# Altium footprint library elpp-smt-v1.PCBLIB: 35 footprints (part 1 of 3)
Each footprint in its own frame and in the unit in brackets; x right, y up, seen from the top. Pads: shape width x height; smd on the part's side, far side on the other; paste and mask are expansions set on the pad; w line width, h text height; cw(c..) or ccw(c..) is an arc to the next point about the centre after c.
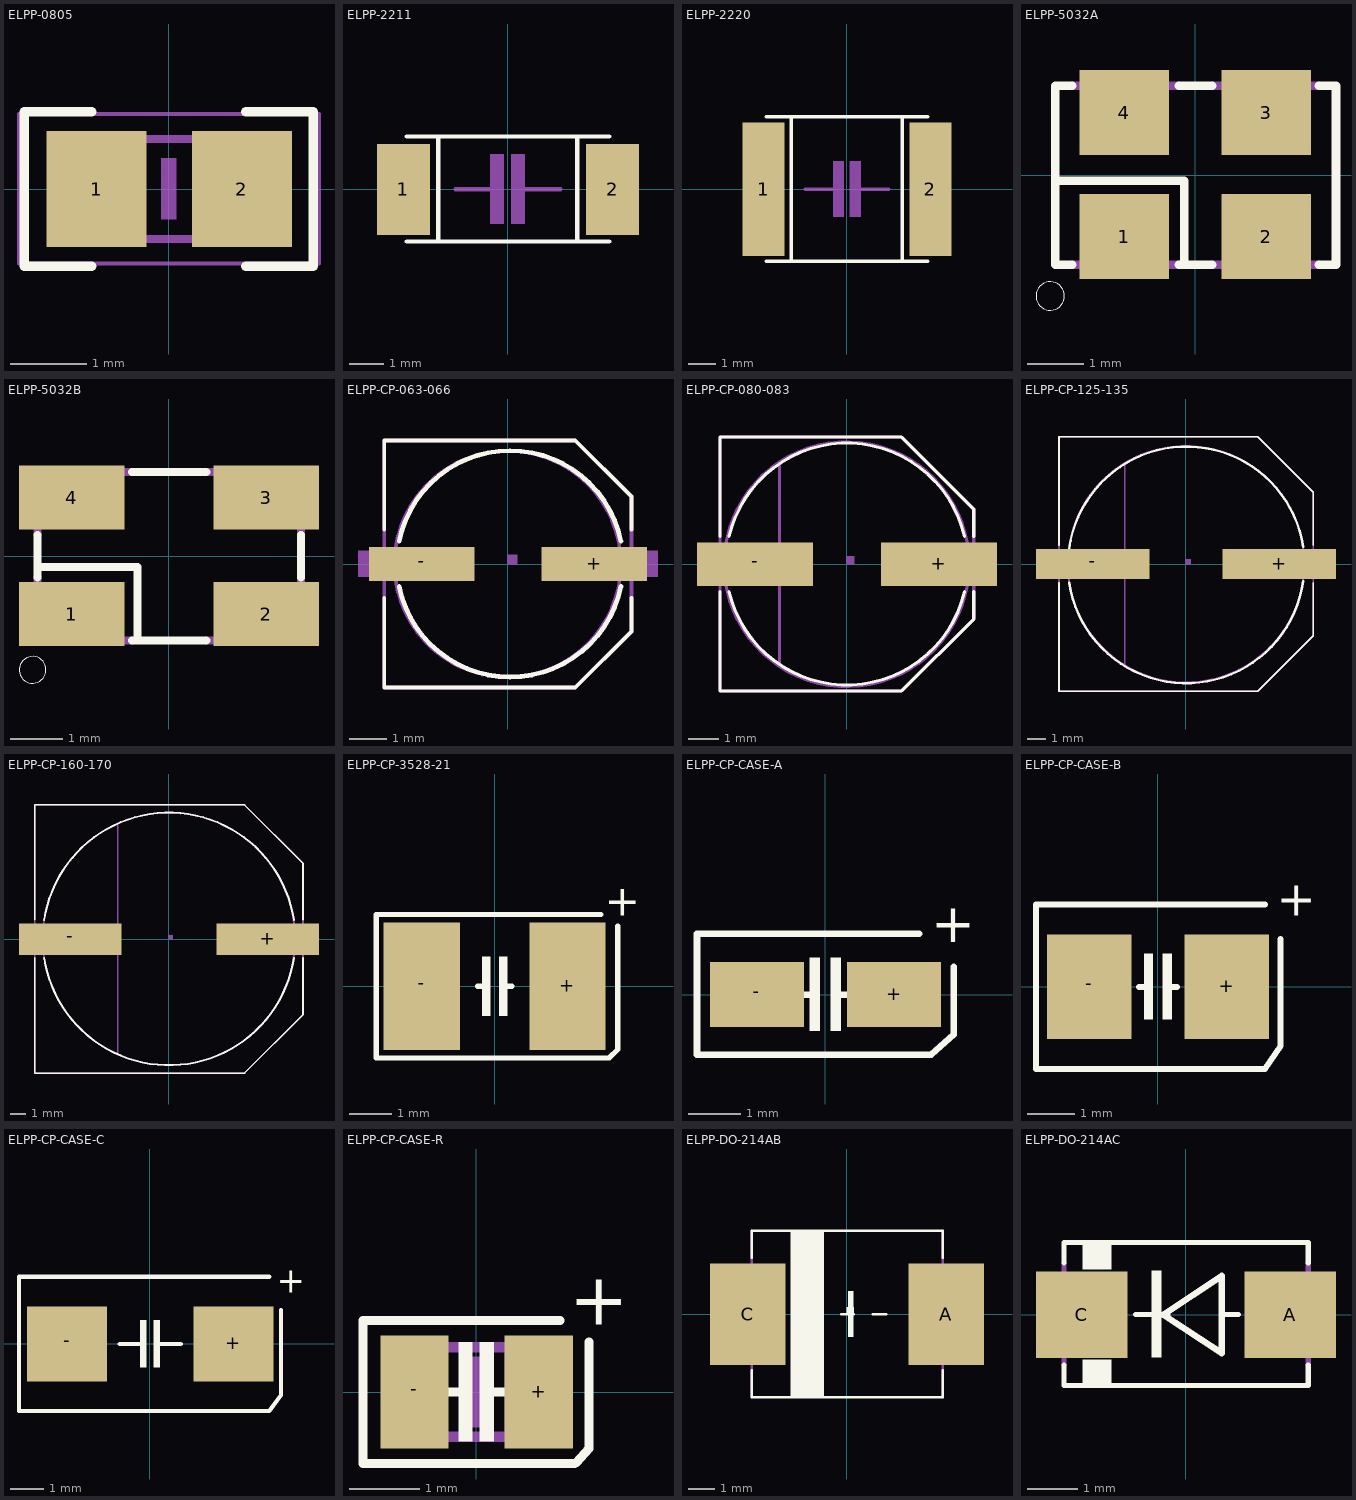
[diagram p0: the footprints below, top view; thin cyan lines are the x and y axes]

## ELPP-0805 [mil]
pads (2):
  rect 52x60 smd: 1(-37.4,0) 2(38,0)
Top Overlay:
  lines w5: -40,-40 -75,-40 -75,40 -40,40 ; 40,-40 75,-40 75,40 40,40
Mechanical 2:
  text ">NAME" at 85,-25 h42.5
Mechanical 4:
  text ">VALUE" at -50,-100 h42.5
Mechanical 6:
  rectangle: -3.94,-15.75 4,16
Mechanical 16:
  rectangle: -43,-28.5 -13.47,29
  rectangle: 14,-28.5 44,29
  lines w4: -15,26 15,26 ; -14.02,-25.98 15,-25.98
Mechanical 27:
  lines w2: -77.68,-38.7 78,-38.7 78,39 -77.68,39 -77.68,-38.7

## ELPP-2211 [mil]
pads (2):
  rect 60x103 smd: 1(-118.11,0) 2(119,0)
Top Overlay:
  lines w5: -114.17,-59.06 -78.74,-59.06 ; -114.17,60 -78.74,60 ; 115,-59.06 79,-59.06 ; 115,60 79,60 ; -78.74,-59.06 79,-59.06 ; -78.74,-59.06 -78.74,60 ; -78.74,60 79,60 ; 79,-59.06 79,60
Mechanical 2:
  text ">NAME" at 158,-23.62 h42.5
Mechanical 4:
  rectangle: 4,-39.37 20,40
  rectangle: -19.68,-39.37 -3.94,40
  lines w5: -59.06,0 -15.75,0 ; 16,0 60,0
  text ">VALUE" at -118.11,-122.05 h42.5

## ELPP-2220 [mil]
pads (2):
  rect 60x189 smd: 1(-118.11,0) 2(119,0)
Top Overlay:
  lines w5: -114.17,-102.36 -78.74,-102.36 ; -114.17,103 -78.74,103 ; 115,-102.36 79,-102.36 ; 115,103 79,103 ; -78.74,-102.36 79,-102.36 ; -78.74,-102.36 -78.74,103 ; -78.74,103 79,103 ; 79,-102.36 79,103
Mechanical 2:
  text ">NAME" at 158,-23.62 h42.5
Mechanical 4:
  rectangle: 4,-39.37 20,40
  rectangle: -19.68,-39.37 -3.94,40
  lines w5: -59.06,0 -15.75,0 ; 16,0 60,0
  text ">VALUE" at -116.93,-160.63 h42.5

## ELPP-5032A [mil]
pads (4):
  rect 63x60 smd: 1(-50,-43.31) 2(50,-43.31) 3(50,44) 4(-50,44)
Top Overlay:
  circle w0: c-102.13,-85.12 r10
  lines w6: -86.61,-62.99 -98.43,-62.99 -98.43,-3.94 ; -86.61,63 -98.43,63 -98.43,-3.94 ; -11.81,-62.99 -7.87,-62.99 ; -11.81,63 12,63 ; 12,-62.99 -7.87,-62.99 ; 87,-62.99 99,-62.99 99,63 87,63 ; -98.43,-3.94 -7.87,-3.94 -7.87,-62.99
Mechanical 2:
  text ">NAME" at 125,-23.23 h42.5
Mechanical 4:
  text ">VALUE" at -70.31,-134.17 h42.5
Mechanical 16:
  lines w6: -86.61,-62.99 -11.81,-62.99 ; -86.61,63 -11.81,63 ; 12,-62.99 87,-62.99 ; 12,63 87,63

## ELPP-5032B [mil]
pads (4):
  rect 79x48 smd: 1(-72.83,-43.31) 2(73,-43.31) 3(73,44) 4(-72.83,44)
Top Overlay:
  circle w0: c-102.13,-85.12 r10
  lines w6: -98.43,-15.75 -98.43,-7.87 ; -98.43,16 -98.43,-7.87 ; -27.56,-62.99 -23.62,-62.99 ; -27.56,63 28,63 ; 28,-62.99 -23.62,-62.99 ; 99,-15.75 99,16 ; -98.43,-7.87 -23.62,-7.87 -23.62,-62.99
Mechanical 2:
  text ">NAME" at 125,-23.23 h42.5
Mechanical 4:
  text ">VALUE" at -70.31,-134.17 h42.5
Mechanical 16:
  lines w6: -98.43,-15.75 -98.43,-62.99 -27.56,-62.99 ; -98.43,16 -98.43,63 -27.56,63 ; 28,-62.99 99,-62.99 99,-15.75 ; 28,63 99,63 99,16

## ELPP-CP-063-066 [mil]
pads (2):
  rect 111x36 smd: +(91,0) -(-90.55,0)
Top Overlay:
  lines w4: -129.92,-35.43 -129.92,-129.92 71,-129.92 130,-70.87 130,-35.43 ; -129.92,36 -129.92,130 71,130 130,71 130,36
  lines w5: -114.17,-23.62 ccw(c2.41,0.09) 119,-23.62 ; -114.17,24 cw(c2.41,0.29) 119,24
Mechanical 2:
  text ">NAME" at 174,-23.62 h42.5
Mechanical 4:
  text ">VALUE" at -70.87,-87.6 h42.5
Mechanical 16:
  circle w4: c0,0 r119
  rectangle: -157.48,-13.78 -129.92,14
  rectangle: 130,-13.78 158,14
  region: 0,0 10,0 10,10 0,10
  lines w4: -129.92,-129.92 71,-129.92 130,-70.87 130,71 71,130 -129.92,130 -129.92,-129.92

## ELPP-CP-080-083 [mil]
pads (2):
  rect 150x56 smd: +(119,0) -(-118.11,0)
Top Overlay:
  lines w4: -163.39,-35.43 -163.39,-163.39 71,-163.39 164,-70.87 164,-35.43 ; -163.39,36 -163.39,164 71,164 164,71 164,36 ; -151.57,-35.43 ccw(c0.21,0.05) 152,-35.43 ; -151.57,36 cw(c0.21,0.52) 152,36
Mechanical 2:
  text ">NAME" at 209,-23.62 h42.5
Mechanical 4:
  text ">VALUE" at -70.87,-87.6 h42.5
Mechanical 16:
  circle w4: c0,0 r158
  rectangle: -177.17,-13.78 -149.61,14
  rectangle: 150,-13.78 178,14
  region: 0,0 10,0 10,10 0,10
  lines w4: -86.61,-127.95 -86.61,128 ; -163.39,-163.39 71,-163.39 164,-70.87 164,71 71,164 -163.39,164 -163.39,-163.39

## ELPP-CP-125-135 [mil]
pads (2):
  rect 237x63 smd: +(195,0) -(-194.88,0)
Top Overlay:
  lines w4: -265.75,-39.37 -265.75,-265.75 150,-265.75 266,-149.61 266,-39.37 ; -265.75,40 -265.75,266 150,266 266,150 266,40
  lines w5: -244.09,-39.37 ccw(c0.17,-1.91) 245,-35.43 ; -244.09,32 cw(c0.74,-1.5) 245,36
Mechanical 2:
  text ">NAME" at 329,-25.59 h42.5
Mechanical 4:
  text ">VALUE" at -100.39,-105.31 h42.5
Mechanical 16:
  circle w4: c0,0 r247
  rectangle: -285.43,-17.72 -248.03,18
  rectangle: 249,-17.72 286,18
  region: 0,0 10,0 10,10 0,10
  lines w4: -127.95,-210.63 -127.95,209 ; -265.75,-265.75 150,-265.75 266,-149.61 266,150 150,266 -265.75,266 -265.75,-265.75

## ELPP-CP-160-170 [mil]
pads (2):
  rect 256x79 smd: +(247,0) -(-246.06,0)
Top Overlay:
  lines w4: -334.65,-47.24 -334.65,-334.65 189,-334.65 335,-188.98 335,-47.24 ; -334.65,48 -334.65,335 189,335 335,189 335,48
  lines w5: -311.02,-47.24 ccw(c0.49,0.07) 312,-47.24 ; -311.02,48 cw(c0.49,0.68) 312,48
Mechanical 2:
  text ">NAME" at 396,-25.59 h42.5
Mechanical 4:
  text ">VALUE" at -100.39,-105.31 h42.5
Mechanical 16:
  circle w4: c0,0 r315
  rectangle: -352.36,-17.72 -314.96,18
  rectangle: 315,-17.72 353,18
  region: 0,0 10,0 10,10 0,10
  lines w4: -127.95,-285.43 -127.95,284 ; -334.65,-334.65 189,-334.65 335,-188.98 335,189 189,335 -334.65,335 -334.65,-334.65

## ELPP-CP-3528-21 [mil]
pads (2):
  rect 71x119 smd: +(68,0) -(-67.91,0)
Top Overlay:
  rectangle: -11.81,-27.56 -3.94,28
  rectangle: 4,-27.56 12,28
  lines w5: -15.75,0 -7.87,0 ; 8,0 16,0 ; 99,67 -110.24,67 -110.24,-66.93 107,-66.93 115,-59.06 115,56
  text "+" at 103,56 h49.6
Mechanical 2:
  text ">NAME" at 123,-26.97 h42.5
Mechanical 4:
  text ">VALUE" at -109.65,-127.56 h42.5

## ELPP-CP-CASE-A [mil]
pads (2):
  rect 71x49 smd: +(52,0) -(-51.57,0)
Top Overlay:
  rectangle: -11.81,-27.56 -3.94,28
  rectangle: 4,-27.56 12,28
  lines w5: -15.75,0 -7.87,0 ; 8,0 16,0 ; 71,46 -96.85,46 -96.85,-45.28 80,-45.28 97,-30.16 97,21
  text "+" at 80,30 h49.6
Mechanical 2:
  text ">NAME" at 111,-25 h42.5
Mechanical 4:
  text ">VALUE" at -80.12,-116.06 h42.5

## ELPP-CP-CASE-B [mil]
pads (2):
  rect 71x88 smd: +(58,0) -(-57.48,0)
Top Overlay:
  rectangle: -11.81,-27.56 -3.94,28
  rectangle: 4,-27.56 12,28
  lines w5: -15.75,0 -7.87,0 ; 8,0 16,0 ; 90,69 -102.36,69 -102.36,-68.9 90,-68.9 103,-49.84 103,40
  text "+" at 100,50 h49.6
Mechanical 2:
  text ">NAME" at 121,-25 h42.5
Mechanical 4:
  text ">VALUE" at -80.12,-135.75 h42.5

## ELPP-CP-CASE-C [mil]
pads (2):
  rect 94x88 smd: +(98,0) -(-97.24,0)
Top Overlay:
  rectangle: -11.81,-27.56 -3.94,28
  rectangle: 4,-27.56 12,28
  lines w5: -35.43,0 -7.87,0 ; 8,0 36,0 ; 140,79 -153.94,79 -153.94,-78.74 140,-78.74 154,-59.69 154,40
  text "+" at 149,50 h49.6
Mechanical 2:
  text ">NAME" at 170,-25 h42.5
Mechanical 4:
  text ">VALUE" at -139.17,-135.75 h42.5

## ELPP-CP-CASE-R [mil]
pads (2):
  rect 38x63 smd: +(35,0) -(-34.45,0)
Top Overlay:
  rectangle: -9.84,-27.56 -1.97,28
  rectangle: 2,-27.56 10,28
  lines w5: -15.75,0 -7.87,0 ; 8,0 16,0 ; 47,40 -63.19,40 -63.19,-40 55,-40 ; 56,-39.37 63,-31.5 63,28
  text "+" at 52,28 h49.6
Mechanical 2:
  text ">NAME" at 76,-25 h42.5
Mechanical 4:
  text ">VALUE" at -60.43,-96.06 h42.5
Mechanical 6:
  rectangle: -7.87,-19.69 8,20
Mechanical 16:
  rectangle: 16,-27.5 42,28
  rectangle: -42,-27.5 -16.41,28
  lines w6: -16.14,-25 17,-25 ; -16.14,25 17,25

## ELPP-DO-214AB [mil]
pads (2):
  rect 111x150 smd: A(146,0) C(-145.67,0)
Top Overlay:
  rectangle: -82.68,-122.05 -33.46,123
  rectangle: 2,-33.46 10,34
  region: 0,0 10,0 10,10 0,10
  lines w4: -140.18,-82.68 -140.18,-122.24 141,-122.24 141,-82.68 ; -140.18,83 -140.18,123 141,123 141,83 ; -7.87,0 10,0 ; 38,0 58,0
Mechanical 2:
  text ">NAME" at 215,-25.24 h42.5
Mechanical 4:
  text ">VALUE" at -136.18,-182.24 h42.5
Mechanical 16:
  rectangle: -161.18,-43 -140.18,43
  rectangle: 141,-43 162,43
  lines w4: -140.18,-122.24 -140.18,123 ; 141,-122.24 141,123

## ELPP-DO-214AC [mil]
pads (2):
  rect 71x67 smd: A(81,0) C(-80.71,0)
Top Overlay:
  rectangle: -26.65,-33.46 -18.78,34
  rectangle: -80,35 -57.5,55
  rectangle: -80,-55 -57.5,-35
  lines w4: -94.49,-39.37 -94.49,-55.12 95,-55.12 95,-39.37 ; -94.49,40 -94.49,56 95,56 95,40 ; -39,0 -17.5,0 -13.78,0 ; 29,0 41,0
  lines w5: -17.5,0 28,30 28,-30 -17.5,0
Mechanical 2:
  text ">NAME" at 127,-24.11 h42.5
Mechanical 4:
  text ">VALUE" at -93.5,-112.5 h42.5
Mechanical 16:
  lines w4: -94.49,-39.37 -94.49,40 ; 95,-39.37 95,40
